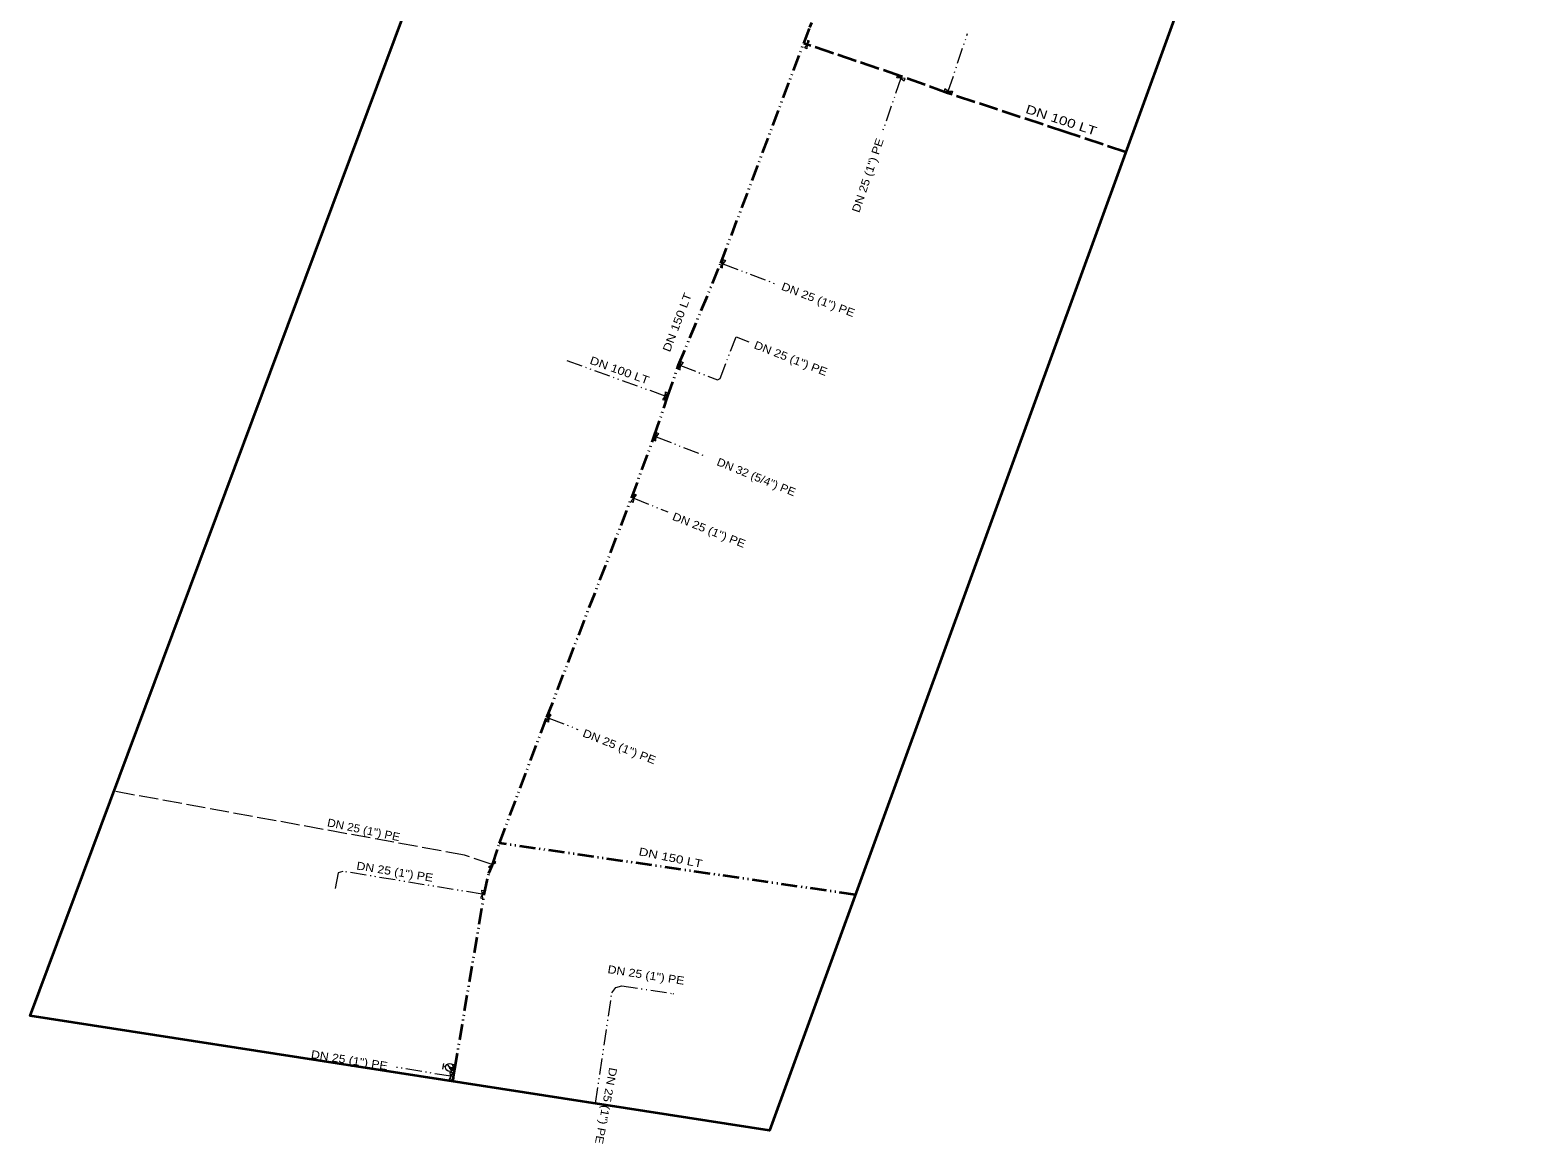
# Model space of a CAD drawing. Extents: x -644344 to -644155, y -1042441 to -1042139.
# Drawn here: x -644344 to -644155.2, y -1042441.1 to -1042301.7 of the extents above; entities that cross this region are included whole.
import ezdxf
from ezdxf.enums import TextEntityAlignment as Align

# ---------------------------------------------------------------- set-up
doc = ezdxf.new("R2010")
doc.units = 0
doc.header["$LTSCALE"] = 0.4
doc.linetypes.add('DASH_DOUBLE_DOT', pattern=[9.2, 5, -1.2, 0.3, -1.2, 0.3, -1.2])
doc.linetypes.add('LONG_DASHED', pattern=[7.5, 6, -1.5])
for name, color, linetype, lineweight in [('10', 7, 'Continuous', 13), ('21', 7, 'LONG_DASHED', 35), ('22', 7, 'DASH_DOUBLE_DOT', 35), ('31', 7, 'LONG_DASHED', 13), ('32', 7, 'DASH_DOUBLE_DOT', 13), ('63', 7, 'Continuous', 35)]:
    doc.layers.add(name, color=color, linetype=linetype, lineweight=lineweight)
doc.layers.add('29', color=7, linetype='Continuous')
doc.layers.add('39', color=7, linetype='Continuous')

msp = doc.modelspace()

# ---------------------------------------------------------------- linework, layer by layer
at = {"layer": '10'}
for p, q in [((-644292.291, -1042431.688), (-644292.163, -1042431)), ((-644291.932, -1042431.399), (-644292.227, -1042431.344)), ((-644291.157, -1042431.903), (-644291.723, -1042431.078))]:
    msp.add_line(p, q, dxfattribs=at)
for points in [[(-644246.643, -1042302.929), (-644246.698, -1042303.972), (-644246.98, -1042303.87), (-644246.36, -1042303.03)], [(-644234.42, -1042307.721), (-644235.46, -1042307.638), (-644235.352, -1042307.359), (-644234.528, -1042308.001)], [(-644229.521, -1042309.273), (-644228.478, -1042309.308), (-644228.574, -1042309.592), (-644229.425, -1042308.989)], [(-644257.269, -1042331.41), (-644257.191, -1042330.369), (-644256.911, -1042330.477), (-644257.549, -1042331.303)], [(-644262.584, -1042344.159), (-644262.48, -1042343.121), (-644262.203, -1042343.235), (-644262.862, -1042344.045)], [(-644264.487, -1042347.975), (-644264.431, -1042346.933), (-644264.149, -1042347.034), (-644264.769, -1042347.874)], [(-644265.609, -1042353.061), (-644265.551, -1042352.019), (-644265.269, -1042352.121), (-644265.891, -1042352.959)], [(-644268.334, -1042359.721), (-644268.445, -1042360.76), (-644268.722, -1042360.643), (-644268.058, -1042359.838)], [(-644278.996, -1042387.236), (-644279.05, -1042388.279), (-644279.332, -1042388.178), (-644278.714, -1042387.337)], [(-644285.891, -1042405.64), (-644286.34, -1042406.582), (-644286.563, -1042406.381), (-644285.669, -1042405.841)], [(-644287.294, -1042410.329), (-644287.406, -1042409.291), (-644287.111, -1042409.346), (-644287.589, -1042410.275)], [(-644291.1, -1042431.122), (-644290.96, -1042432.157), (-644291.257, -1042432.11), (-644290.804, -1042431.169)], [(-644291.239, -1042433.117), (-644291.381, -1042432.083), (-644291.084, -1042432.129), (-644291.535, -1042433.071)]]:
    msp.add_lwpolyline(points, close=True, dxfattribs=at)
msp.add_circle((-644291.4406, -1042431.4898), 0.5, dxfattribs=at)
at = {"layer": '21'}
for p, q in [((-644246.67, -1042303.45), (-644247.1, -1042303.309)), ((-644234.859, -1042307.441), (-644246.67, -1042303.45)), ((-644229.078, -1042309.529), (-644234.859, -1042307.441)), ((-644291.44, -1042431.49), (-644291.03, -1042431.64)), ((-644291.03, -1042431.64), (-644290.784, -1042431.682))]:
    msp.add_line(p, q, dxfattribs=at)
msp.add_lwpolyline([(-644206.772, -1042316.912), (-644214.284, -1042314.426), (-644229.078, -1042309.529)], dxfattribs=at)
at = {"layer": '22'}
for p, q in [((-644257.463, -1042330.801), (-644247.1, -1042303.309)), ((-644262.764, -1042343.548), (-644257.463, -1042330.801)), ((-644264.141, -1042347.568), (-644262.764, -1042343.548)), ((-644265.815, -1042352.455), (-644264.141, -1042347.568)), ((-644268.622, -1042360.151), (-644265.815, -1042352.455)), ((-644279.256, -1042387.666), (-644268.622, -1042360.151)), ((-644285.187, -1042403.419), (-644279.256, -1042387.666)), ((-644240.627, -1042409.886), (-644285.187, -1042403.419)), ((-644290.784, -1042431.682), (-644287.104, -1042409.855)), ((-644290.957, -1042432.655), (-644290.784, -1042431.682)), ((-644291.011, -1042433.235), (-644290.957, -1042432.655))]:
    msp.add_line(p, q, dxfattribs=at)
for points in [[(-644247.1, -1042303.309), (-644246.322, -1042301.292), (-644246.098, -1042300.677), (-644246.098, -1042300.677)], [(-644287.104, -1042409.855), (-644286.524, -1042407.182), (-644286.09, -1042406.12), (-644285.187, -1042403.419)]]:
    msp.add_lwpolyline(points, dxfattribs=at)
at = {"layer": '31'}
msp.add_line((-644286.09, -1042406.12), (-644286.116, -1042406.111), dxfattribs=at)
msp.add_lwpolyline([(-644286.116, -1042406.111), (-644289.57, -1042404.92), (-644333.475, -1042396.924)], dxfattribs=at)
at = {"layer": '32'}
for p, q in [((-644229, -1042309.29), (-644226.591, -1042302.07)), ((-644234.94, -1042307.68), (-644237.304, -1042314.511)), ((-644234.859, -1042307.441), (-644234.94, -1042307.68)), ((-644229.078, -1042309.529), (-644229, -1042309.29)), ((-644264.459, -1042347.454), (-644276.884, -1042342.986)), ((-644279.256, -1042387.666), (-644279.023, -1042387.757)), ((-644279.023, -1042387.757), (-644275.39, -1042389.174)), ((-644287.104, -1042409.855), (-644287.35, -1042409.81)), ((-644263.495, -1042422.246), (-644263.403, -1042422.26)), ((-644291.31, -1042432.6), (-644298.433, -1042431.428)), ((-644290.957, -1042432.655), (-644291.31, -1042432.6))]:
    msp.add_line(p, q, dxfattribs=at)
for points in [[(-644257.463, -1042330.801), (-644257.23, -1042330.89), (-644250.603, -1042333.426)], [(-644262.532, -1042343.64), (-644257.891, -1042345.416), (-644257.581, -1042345.253), (-644255.559, -1042340.036), (-644253.98, -1042340.651)], [(-644262.764, -1042343.548), (-644262.692, -1042343.576), (-644262.532, -1042343.64)], [(-644264.141, -1042347.568), (-644264.459, -1042347.454), (-644264.459, -1042347.454)], [(-644265.815, -1042352.455), (-644265.58, -1042352.54), (-644259.297, -1042355.01)], [(-644268.622, -1042360.151), (-644268.39, -1042360.24), (-644264.112, -1042361.964)], [(-644287.35, -1042409.81), (-644304.817, -1042406.949), (-644305.404, -1042407.122), (-644305.863, -1042409.467)], [(-644273.174, -1042436), (-644271.134, -1042422.157), (-644270.616, -1042421.502), (-644269.891, -1042421.26), (-644263.495, -1042422.246)]]:
    msp.add_lwpolyline(points, dxfattribs=at)
at = {"layer": '63'}
msp.add_lwpolyline([(-644237.01, -1042138.605), (-644155.176, -1042175.215), (-644251.367, -1042439.381), (-644343.968, -1042425.024)], close=True, dxfattribs=at)

# ---------------------------------------------------------------- texts
at = {"layer": '29'}
for s, height, rotation, width, p in [('DN 100 LT', 1.1, 341.86, 1.3, (-644215.0232, -1042313.427)), ('DN 150 LT', 1, 69.159, 1.2, (-644262.4828, -1042338.4019)), ('DN 150 LT', 1, 348.618, 1.25, (-644263.8667, -1042405.7169))]:
    msp.add_text(s, height=height, rotation=rotation, dxfattribs=dict(at, width=width)).set_placement(p, align=Align.CENTER)
at = {"layer": '39'}
for s, rotation, width, p in [('DN 25 (1") PE', 71.392, 1.15, (-644238.6072, -1042319.9885)), ('DN 25 (1") PE', 339.055, 1.15, (-644245.4707, -1042335.8521)), ('DN 25 (1") PE', 338.824, 1.15, (-644248.9056, -1042343.2053)), ('DN 100 LT', 340.222, 1.2, (-644270.3322, -1042344.6944)), ('DN 32 (5/4") PE', 337.956, 1.1, (-644253.2197, -1042358.0449)), ('DN 25 (1") PE', 338.435, 1.15, (-644259.1428, -1042364.696)), ('DN 25 (1") PE', 338.692, 1.15, (-644270.3647, -1042391.7964)), ('DN 25 (1") PE', 348.265, 1.1, (-644302.3007, -1042402.2327)), ('DN 25 (1") PE', 350.75, 1.15, (-644298.3814, -1042407.4827)), ('DN 25 (1") PE', 351.236, 1.15, (-644266.9222, -1042420.4066)), ('DN 25 (1") PE', 350.992, 1.15, (-644304.0713, -1042431.0612)), ('DN 25 (1") PE', 259.216, 1.15, (-644272.34, -1042436.2035))]:
    msp.add_text(s, height=1, rotation=rotation, dxfattribs=dict(at, width=width)).set_placement(p, align=Align.CENTER)

doc.saveas('drawing.dxf')
